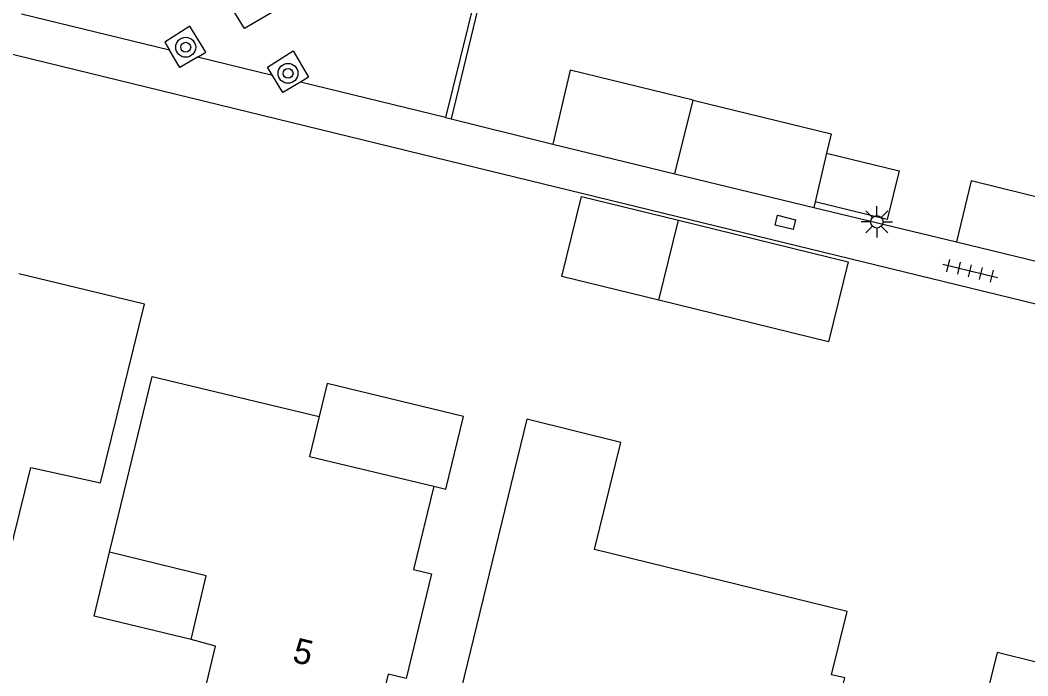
# Model space of a CAD drawing. Extents: x 125000 to 129004, y 397500 to 399008.
# Drawn here: x 126482.61 to 126522.99, y 398505.38 to 398531.64 of the extents above; entities that cross this region are included whole.
import ezdxf

# ---------------------------------------------------------------- set-up
doc = ezdxf.new("R2010")
doc.units = 0
for name, color, linetype in [('gg-afsc-erfafscheiding', 7, 'Continuous'), ('gg-afsc-hekwerk', 7, 'Continuous'), ('gg-anno-huisnummerreeks BGT', 7, 'Continuous'), ('gg-bbg-bijgebouw', 7, 'Continuous'), ('gg-bbg-gedigitaliseerde bijgebouw', 7, 'Continuous'), ('gg-bbg-hoofdgebouw', 7, 'Continuous'), ('gg-bbg-luifel en loopbrug', 7, 'Continuous'), ('gg-bbg-tussenscheiding', 7, 'Continuous'), ('gg-knt-verharding', 7, 'Continuous'), ('gt-grn-weggrens', 7, 'Continuous'), ('gt-symb-boom', 7, 'Continuous'), ('gt-symb-kolk center center', 7, 'Continuous'), ('gt-symb-lichtmast', 7, 'Continuous'), ('gt-symb-tegel verharding', 7, 'Continuous')]:
    doc.layers.add(name, color=color, linetype=linetype)

# ---------------------------------------------------------------- blocks, each defined once
blk = doc.blocks.new('gt0-BOOM')
at = {"layer": 'gt-symb-boom'}
for radius in [0.4, 0.2]:
    blk.add_circle((0, 0), radius, dxfattribs=at)
blk = doc.blocks.new('gt0-KOLKCC')
at = {"layer": 'gt-symb-kolk center center'}
blk.add_lwpolyline([(-0.375, 0.2), (0.375, 0.2), (0.375, -0.2), (-0.375, -0.2)], close=True, dxfattribs=at)
blk = doc.blocks.new('gt0-LMAST')
at = {"layer": 'gt-symb-lichtmast'}
for p, q in [((-0.182, 0.173), (-0.447, 0.438)), ((-0.005, 0.246), (-0.005, 0.621)), ((0.172, 0.173), (0.437, 0.438)), ((-0.255, -0.004), (-0.63, -0.004)), ((-0.182, -0.181), (-0.447, -0.446)), ((-0.005, -0.254), (-0.005, -0.629)), ((0.437, -0.446), (0.172, -0.181)), ((0.245, -0.004), (0.62, -0.004))]:
    blk.add_line(p, q, dxfattribs=at)
blk.add_circle((-0.005, -0.004), 0.25, dxfattribs=at)
blk = doc.blocks.new('gt0-TEG1')
at = {"layer": 'gt-symb-tegel verharding'}
for p, q in [((-1.125, 0), (1.125, 0)), ((-0.9, -0.25), (-0.9, 0.25)), ((-0.45, -0.25), (-0.45, 0.25)), ((0, -0.25), (0, 0.25)), ((0.45, -0.25), (0.45, 0.25)), ((0.9, -0.25), (0.9, 0.25))]:
    blk.add_line(p, q, dxfattribs=at)

msp = doc.modelspace()

# ---------------------------------------------------------------- linework, layer by layer
at = {"layer": 'gg-afsc-erfafscheiding'}
for p, q in [((126499.647, 398527.735), (126499.876, 398527.68)), ((126499.876, 398527.68), (126503.956, 398526.675)), ((126514.413, 398524.13), (126520.126, 398522.764))]:
    msp.add_line(p, q, dxfattribs=at)
at = {"layer": 'gg-afsc-hekwerk'}
for p, q in [((126502.93, 398540.299), (126499.876, 398527.68)), ((126499.249, 398526.124), (126481.914, 398530.358))]:
    msp.add_line(p, q, dxfattribs=at)
at = {"layer": 'gg-bbg-bijgebouw'}
for p, q in [((126509.579, 398528.432), (126515.104, 398527.087)), ((126503.956, 398526.675), (126508.847, 398525.485)), ((126508.847, 398525.485), (126514.413, 398524.13))]:
    msp.add_line(p, q, dxfattribs=at)
msp.add_lwpolyline([(126509.579, 398528.432), (126504.647, 398529.632), (126503.956, 398526.675)], dxfattribs=at)
at = {"layer": 'gg-bbg-gedigitaliseerde bijgebouw'}
for p, q in [((126515.104, 398527.087), (126514.922, 398526.308)), ((126514.467, 398524.36), (126514.413, 398524.13)), ((126508.201, 398520.416), (126508.987, 398523.621)), ((126520.126, 398522.764), (126523.479, 398521.942))]:
    msp.add_line(p, q, dxfattribs=at)
for points in [[(126514.922, 398526.308), (126517.828, 398525.597), (126517.352, 398523.654), (126514.467, 398524.36)], [(126524.077, 398524.38), (126520.723, 398525.201), (126520.126, 398522.764)], [(126508.201, 398520.416), (126504.316, 398521.369), (126505.102, 398524.574), (126508.987, 398523.621)]]:
    msp.add_lwpolyline(points, dxfattribs=at)
at = {"layer": 'gg-bbg-hoofdgebouw'}
for p, q in [((126487.589, 398520.262), (126482.558, 398521.476)), ((126486.186, 398510.33), (126487.893, 398517.368)), ((126487.893, 398517.368), (126494.591, 398515.769))]:
    msp.add_line(p, q, dxfattribs=at)
for points in [[(126475.782, 398517.478), (126473.218, 398507.277), (126474.359, 398506.995), (126474.123, 398506.013), (126477.334, 398505.242), (126477.578, 398506.199), (126480.968, 398505.374), (126483.031, 398513.722), (126485.829, 398513.111), (126487.589, 398520.262)], [(126494.591, 398515.769), (126494.208, 398514.165), (126499.181, 398512.968)], [(126500.029, 398503.81), (126503.476, 398502.98), (126502.777, 398500.038), (126513.21, 398497.498), (126514.852, 398504.303), (126515.381, 398504.174), (126515.651, 398505.294), (126515.126, 398505.421), (126515.747, 398507.954), (126505.626, 398510.436), (126506.682, 398514.728), (126502.915, 398515.655), (126500.029, 398503.81)], [(126499.181, 398512.968), (126498.369, 398509.632), (126499.094, 398509.456), (126498.075, 398505.269), (126497.35, 398505.446), (126496.422, 398501.636), (126493.858, 398502.241), (126493.571, 398501.094), (126490.253, 398501.902), (126490.509, 398503.069), (126489.646, 398503.266), (126490.436, 398506.568), (126489.462, 398506.831)], [(126489.462, 398506.831), (126490.066, 398509.377), (126486.186, 398510.33)], [(126520.194, 398500), (126519.453, 398497.003), (126521.2, 398496.571), (126520.646, 398494.436), (126524.803, 398493.418), (126525.086, 398494.574), (126528.576, 398493.736), (126529.565, 398497.702), (126533.376, 398496.752), (126535.303, 398504.481), (126526.974, 398506.558), (126526.612, 398505.106), (126521.756, 398506.317), (126520.194, 398500)]]:
    msp.add_lwpolyline(points, dxfattribs=at)
at = {"layer": 'gg-bbg-luifel en loopbrug'}
for points in [[(126508.987, 398523.621), (126515.786, 398521.954), (126515, 398518.749), (126508.201, 398520.416)], [(126499.181, 398512.968), (126499.667, 398512.851), (126500.371, 398515.767), (126494.909, 398517.085), (126494.591, 398515.769)], [(126489.462, 398506.831), (126485.568, 398507.771), (126486.186, 398510.33)]]:
    msp.add_lwpolyline(points, dxfattribs=at)
at = {"layer": 'gg-bbg-tussenscheiding'}
for p, q in [((126508.847, 398525.485), (126509.579, 398528.432)), ((126514.922, 398526.308), (126514.467, 398524.36))]:
    msp.add_line(p, q, dxfattribs=at)
at = {"layer": 'gg-knt-verharding'}
for p, q in [((126505.577, 398551.748), (126499.647, 398527.735)), ((126546.889, 398514.521), (126499.249, 398526.124))]:
    msp.add_line(p, q, dxfattribs=at)
for points in [[(126491.602, 398531.297), (126490.032, 398533.846), (126492.323, 398535.228), (126493.908, 398532.671), (126491.602, 398531.297)], [(126489.711, 398530.158), (126490.047, 398530.358), (126489.41, 398531.394), (126488.404, 398530.754), (126488.597, 398530.43)], [(126489.711, 398530.158), (126489.007, 398529.74), (126488.597, 398530.43)], [(126492.715, 398529.425), (126492.515, 398529.756), (126493.543, 398530.402), (126494.161, 398529.347), (126493.836, 398529.152)], [(126493.836, 398529.152), (126493.135, 398528.733), (126492.715, 398529.425)]]:
    msp.add_lwpolyline(points, dxfattribs=at)
at = {"layer": 'gt-grn-weggrens'}
for p, q in [((126488.597, 398530.43), (126482.654, 398531.879)), ((126492.715, 398529.425), (126489.711, 398530.158)), ((126499.647, 398527.735), (126493.836, 398529.152))]:
    msp.add_line(p, q, dxfattribs=at)

# ---------------------------------------------------------------- block references
at = {"layer": 'gt-symb-boom'}
for p in [(126489.24, 398530.551), (126493.341, 398529.507)]:
    msp.add_blockref('gt0-BOOM', p, dxfattribs=at)
at = {"layer": 'gt-symb-kolk center center', "rotation": -13.535856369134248}
msp.add_blockref('gt0-KOLKCC', (126513.274, 398523.539), dxfattribs=at)
at = {"layer": 'gt-symb-lichtmast'}
msp.add_blockref('gt0-LMAST', (126516.943, 398523.564), dxfattribs=at)
at = {"layer": 'gt-symb-tegel verharding', "rotation": -13.59156044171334}
msp.add_blockref('gt0-TEG1', (126520.675, 398521.595), dxfattribs=at)

# ---------------------------------------------------------------- texts
at = {"layer": 'gg-anno-huisnummerreeks BGT'}
msp.add_text('5', height=1, rotation=346.5, dxfattribs=at).set_placement((126493.475, 398505.945))

doc.saveas('drawing.dxf')
